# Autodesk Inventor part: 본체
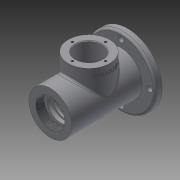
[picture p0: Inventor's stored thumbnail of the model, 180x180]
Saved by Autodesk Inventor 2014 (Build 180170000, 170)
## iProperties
Created: 2016-08
Part Number: 본체
Material: 일반
Document SubType Name: Modeling
Designer: USER
Density: 1 g/cm^3
Appearance: 기본값
Author: USER
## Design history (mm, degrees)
sketch "스케치1"
  geometry: L1 (-57.5, 0)-(57.5, 0); L2 (-57.5, 0)-(-57.5, 31); L3 (-57.5, 31)-(57.5, 31); L4 (57.5, 31)-(57.5, 0); 2 further points
  constraints: 8 end point, 3 perpendicular, 1 coincident, 1 horizontal, 1 horizontal alignment, 1 midpoint
  dimensions: "d0" = 115 distance between parallel lines of L4 L2; "d1" = 62 diameter of L3 L1
revolve "회전1" sketch "스케치1" stored, may be unused: angle "d2" = 90 deg
node "작업 평면1"
sketch "스케치2"
  geometry: C1 r 50 at (0, 0); 1 further point
  constraints: 1 centre point, 1 coincident
  dimensions: "d4" = 100 diameter of C1
extrude "돌출1" join sketch "스케치2" distance "d5" = 10; taper "d6" = 0 deg
sketch "스케치4"
  geometry: L1 (-57.5, -31)-(-57.5, 31) reference; L2 (57.5, -31)-(57.5, 31) reference; L3 (-57.5, 0)-(57.5, 0); L4 (-57.5, 0)-(-57.5, 21); L5 (-57.5, 21)-(-45.5, 21); L6 (-45.5, 21)-(-45.5, 24); L7 (-45.5, 24)-(-42.5, 24); L8 (-42.5, 24)-(-42.5, 20); L9 (-42.5, 20)-(-36.5, 20); L10 (-36.5, 20)-(-36.5, 17.5); L11 (-36.5, 17.5)-(-33.25, 17.5); L12 (-33.25, 17.5)-(-33.25, 18.5); L13 (-33.25, 18.5)-(-31.5, 18.5); L14 (-31.5, 18.5)-(-31.5, 17.5); L15 (-31.5, 17.5)-(-20.5, 17.5); L16 (57.5, 21)-(43.5, 16); L17 (43.5, 16)-(43.5, 12.5); L18 (43.5, 12.5)-(36.2, 12.5); L19 (36.2, 12.5)-(36.2, 10); L20 (36.2, 10)-(33.5, 10); L21 (33.5, 10)-(33.5, 16.5); L22 (33.5, 16.5)-(28.5, 16.5); L23 (28.5, 16.5)-(28.5, 17.5); L24 (28.5, 17.5)-(17.5, 17.5); L25 (17.5, 17.5)-(17.5, 26); L26 (17.5, 26)-(-20.5, 26); L27 (-20.5, 26)-(-20.5, 17.5); 1 further point
  constraints: 50 end point, 13 parallel, 9 perpendicular, 2 midpoint, 2 point on line, 1 collinear, 1 horizontal alignment
  dimensions: "d35" = 3 distance between parallel lines of L8 L6; "d36" = 12 distance between parallel lines of L1 L6; "d37" = 21 distance between parallel lines of L10 L1; "d38" = 26 distance between parallel lines of L14 L1; "d39" = 1.75 distance between parallel lines of L14 L12; "d40" = 37 diameter of L13 L3; "d41" = 35 diameter of L11 L3; "d42" = 40 diameter of L9 L3; "d43" = 48 diameter of L7 L3; "d44" = 42 diameter of L5 L3; "d45" = 14 distance between parallel lines of L2 L17; "d46" = 7.3 distance between parallel lines of L19 L17; "d47" = 2.7 distance between parallel lines of L19 L21; "d49" = 38 distance between parallel lines of L25 L27; "d50" = 60 distance between parallel lines of L14 L23; "d52" = 52 diameter of L26 L3; "d53" = 35 diameter of L24 L3; "d54" = 33 diameter of L22 L3; "d55" = 20 diameter of L20 L3; "d56" = 25 diameter of L18 L3; "d57" = 32 diameter of L16.end L3; "d58" = 42 diameter of L16.start L3
revolve "회전2" sketch "스케치4" stored, may be unused: angle "d59" = 90 deg
node "작업 평면2"
sketch "스케치5"
  geometry: L1 (31, -57.5)-(-31, -57.5) reference; C1 r 30 at (0, -1.5); 2 further points
  constraints: 1 centre point, 1 midpoint, 1 vertical alignment
  dimensions: "d67" = 60 diameter of C1; "d68" = 56 distance from line of C1.centre L1
extrude "돌출2" join sketch "스케치5" stored distance "d62" = 13; taper "d63" = 0 deg
sketch "스케치9"
  geometry: C1 r 50 at (0, 0) reference; C2 r 31 at (0, 0) reference; C3 r 4 at (0, 41.5); C4 r 4 at (-41.5, 0); C5 r 4 at (0, -41.5); C6 r 4 at (41.5, 0); A1 r 41.5 centre (0, 0) between (0, 41.5) and (-41.5, 0)
  constraints: 5 centre point, 4 point on circle, 2 horizontal alignment, 2 vertical alignment, 1 coincident
  dimensions: "d72" = 83 diameter of A1; "d73" = 8 diameter of C3; "d74" = 8 diameter of C4; "d75" = 8 diameter of C5; "d76" = 8 diameter of C6
extrude "돌출3" cut sketch "스케치9" stored distance "d77" = 13; taper "d78" = 0 deg
node "작업 평면3"
sketch "스케치10"
  geometry: L1 (-30, 0)-(30, 0) reference; L2 (-56, -80)-(-56, -18) reference; 2 further points
  constraints: 1 other
  dimensions: "d79" = 10 distance from line of point (0, -10) L1; "d80" = 56 distance from line of L2 point (0, -10)
feature "엠보싱1" sketch "스케치10" dims "d0" = 115, "d1" = 62, "d35" = 3, "d36" = 12, "d37" = 21, "d38" = 26, "d39" = 1.75, "d40" = 37, "d41" = 35, "d42" = 40, "d43" = 48, "d44" = 42, "d45" = 14, "d46" = 7.3, "d47" = 2.7, "d49" = 38, "d50" = 60, "d52" = 52, "d53" = 35, "d54" = 33, "d55" = 20, "d56" = 25, "d57" = 32, "d58" = 42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
feature "스레드1" dims "d83" = 10, "d84" = 0
fillet "모깎기1" dims "d96" = 3
chamfer "모따기2" distance "d97" = 0.7; stored, may be unused: second distance "d98" = 2, angle "d99" = 30 deg
fillet "모깎기2" dims "d100" = 0.3
fillet "모깎기3" dims "d101" = 3
chamfer "모따기3" distance "d102" = 1; stored, may be unused: second distance "d103" = 2, angle "d104" = 30 deg
chamfer "모따기4" distance "d105" = 1; stored, may be unused: second distance "d106" = 2, angle "d107" = 30 deg
fillet "모깎기4" dims "d108" = 0.3
sketch "스케치18"
  geometry: C1 r 30 at (0, 0) reference; C2 r 19 at (0, 0); 1 further point
  constraints: 1 centre point, 1 coincident
  dimensions: "d110" = 38 diameter of C2
extrude "돌출4" cut sketch "스케치18" distance "d111" = 45; taper "d112" = 0 deg
chamfer "모따기5" distance "d113" = 1; stored, may be unused: second distance "d114" = 2, angle "d115" = 30 deg
fillet "모깎기6" dims "d116" = 3
fillet "모깎기7" dims "d117" = 3
sketch "스케치22"
  geometry: C1 r 30 at (0, 0) reference; C2 r 20 at (0, 0) reference; A1 r 24 centre (0, 0) between (0, 24) and (-24, 0); 3 further points
  constraints: 4 point on circle, 2 horizontal alignment, 2 vertical alignment, 1 centre point, 1 coincident
  dimensions: "d118" = 48 diameter of A1
hole "구멍2" sketch "스케치22" at (0, 24), (-24, 0), (0, -24), (24, 0) diameter "d119" = 3.242; stored, may be unused: countersink angle "d123" = 90 deg, drill point angle "d125" = 118 deg; dims "d120" = 8, "d121" = 4, "d122" = 2, "d124" = 10
fillet "모깎기8" dims "d126" = 3
node "솔리드1"
other parameters: "d3" = -3, "d60" = 49
